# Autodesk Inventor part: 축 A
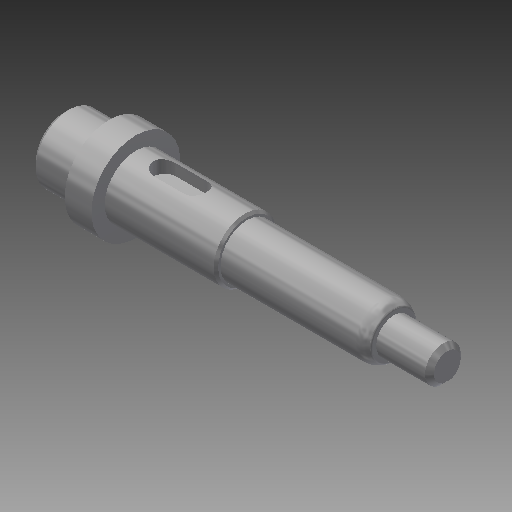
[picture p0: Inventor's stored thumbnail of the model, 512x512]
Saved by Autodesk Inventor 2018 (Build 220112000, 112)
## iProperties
Created: 2020-04
Part Number: 축 A
Material: 강철, 연강
Document SubType Name: Modeling
Designer: mduedu
Density: 7.86 g/cm^3
Mass: 91.1355 g
Surface Area: 41.2026 cm^2
Volume: 11.5948 cm^3
Appearance: 강철
Author: mduedu
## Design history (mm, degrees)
sketch "스케치1"
  geometry: L1 (0, 0)-(10, 0); L2 (10, 0)-(10, 7.5); L3 (10, 7.5)-(0, 7.5); L4 (0, 7.5)-(0, 0); L5 (10, 0)-(16, 0); L6 (16, 0)-(16, 10); L7 (16, 10)-(10, 10); L8 (10, 10)-(10, 0); L9 (16, 0)-(41, 0); L10 (41, 0)-(41, 7); L11 (41, 7)-(16, 7); L12 (16, 7)-(16, 0); L13 (41, 0)-(74, 0); L14 (74, 0)-(74, 6); L15 (74, 6)-(41, 6); L16 (41, 6)-(41, 0); L17 (74, 0)-(86, 0); L18 (86, 0)-(86, 4); L19 (86, 4)-(74, 4); L20 (74, 4)-(74, 0)
  constraints: 40 end point, 10 parallel, 5 horizontal, 5 perpendicular
  dimensions: "d0" = 86 distance between parallel lines of L18 L4; "d2" = 10 distance of L2.end L3.end; "d3" = 6 distance of L6.end L7.end; "d4" = 12 distance of L18.end L19.end; "d5" = 8 diameter of L19 L17; "d6" = 12 diameter of L15 L13; "d7" = 14 diameter of L11 L9; "d8" = 15 diameter of L3 L1; "d9" = 20 diameter of L7 L5; "d10" = 45 distance between parallel lines of L10 L18
revolve "회전1" sketch "스케치1" stored, may be unused: angle "d11" = 90 deg
sketch "스케치2"
  geometry: L1 (0, -7.5)-(0, 7.5) reference; L2 (0, 7.5)-(10, 7.5) reference; L3 (10, 7.5)-(10, 10) reference; L4 (10, 10)-(16, 10) reference; L5 (16, 10)-(16, 7) reference; L6 (16, 7)-(41, 7) reference; L7 (41, 7)-(41, 6) reference; L8 (41, 6)-(74, 6) reference; L9 (74, 6)-(74, 4) reference; L10 (74, 4)-(86, 4) reference; L11 (86, 4)-(86, -4) reference; L12 (86, -4)-(74, -4) reference; L13 (74, -4)-(74, -6) reference; L14 (74, -6)-(41, -6) reference; L15 (41, -6)-(41, -7) reference; L16 (41, -7)-(16, -7) reference; L17 (16, -7)-(16, -10) reference; L18 (16, -10)-(10, -10) reference; L19 (10, -10)-(10, -7.5) reference; L20 (10, -7.5)-(0, -7.5) reference; L21 (86, -4)-(78, -4); L22 (78, -4)-(78, -2.8); L23 (78, -2.8)-(86, -2.8); L24 (86, -2.8)-(86, -4); 1 further point
  constraints: 8 end point, 2 parallel, 1 horizontal, 1 perpendicular
  dimensions: "d12" = 8 distance of L22.end L23.end; "d13" = 1.2 distance of L21.end L22.end
extrude "돌출1" cut sketch "스케치2" stored distance "d14" = 2; taper "d15" = 0 deg
fillet "모깎기1" dims "d16" = 1
sketch "스케치3"
  geometry: L1 (0, -7.5)-(0, 7.5) reference; L2 (0, 7.5)-(10, 7.5) reference; L3 (10, 7.5)-(10, 10) reference; L4 (10, 10)-(16, 10) reference; L5 (16, 10)-(16, 7) reference; L6 (16, 7)-(41, 7) reference; L7 (41, 7)-(41, 6) reference; L8 (41, 6)-(74, 6) reference; L9 (74, 6)-(74, 4) reference; L10 (74, 4)-(86, 4) reference; L11 (86, 4)-(86, -2.8) reference; L12 (86, -2.8)-(78, -2.8) reference; L13 (78, -2.8)-(78, -4) reference; L14 (78, -4)-(74, -4) reference; L15 (74, -4)-(74, -6) reference; L16 (74, -6)-(41, -6) reference; L17 (41, -6)-(41, -7) reference; L18 (41, -7)-(16, -7) reference; L19 (16, -7)-(16, -10) reference; L20 (16, -10)-(10, -10) reference; L21 (10, -10)-(10, -7.5) reference; L22 (10, -7.5)-(0, -7.5) reference; L23 (20, 7)-(32, 7); L24 (32, 7)-(32, 4); L25 (32, 4)-(20, 4); L26 (20, 4)-(20, 7); 1 further point
  constraints: 8 end point, 2 parallel, 1 horizontal, 1 perpendicular, 1 point on line
  dimensions: "d17" = 12 distance of L24.end L25.end; "d18" = 3 distance of L23.end L24.end; "d19" = 4 distance from line of L26 L4.end
extrude "돌출2" cut sketch "스케치3" stored distance "d20" = 5; taper "d21" = 0 deg
fillet "모깎기2" dims "d22" = 2.5
chamfer "모따기1" distance "d23" = 1; stored, may be unused: second distance "d24" = 2, angle "d25" = 45 deg
chamfer "모따기2" distance "d26" = 0.5; stored, may be unused: second distance "d27" = 2, angle "d28" = 45 deg
fillet "모깎기3" dims "d29" = 0.3
chamfer "모따기3" distance "d30" = 1.56; stored, may be unused: second distance "d31" = 2, angle "d32" = 30 deg
fillet "모깎기4" dims "d33" = 4, "d34" = 0.5
node "솔리드1"
node "절단 모서리 투영1"
node "절단 모서리 투영2"
